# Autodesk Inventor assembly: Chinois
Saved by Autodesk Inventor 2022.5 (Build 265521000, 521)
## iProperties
Created: 2024-07
Part Number: Chinois
Document SubType Name: Assembly
Designer: AdminForWorker
Title: Chinois v3
Author: AdminForWorker
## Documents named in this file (2)
- z:\worker\convert-fusion-r03-cosv3\tmp\job-1\32\temp\files\f0bacd61-cbe3-4501-ac2f-e71adfe0b3b0\Chinois v3.iam
- z:\worker\convert-fusion-r03-cosv3\tmp\job-1\32\temp\files\f0bacd61-cbe3-4501-ac2f-e71adfe0b3b0\Chinois.ipt
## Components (1 placed, 1 different names)
1. Chinois:1
